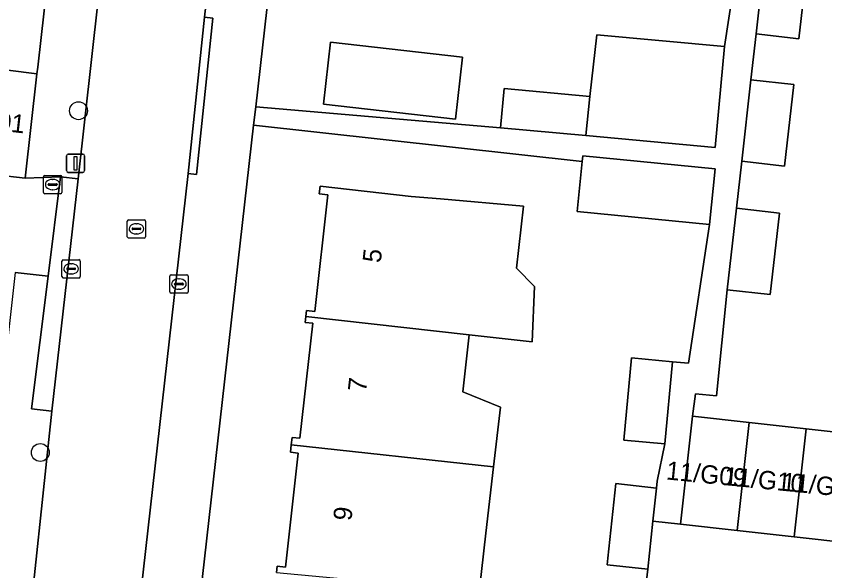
# Model space of a CAD drawing. Extents: x 162396 to 163643, y 386452 to 387406.
# Drawn here: x 162508.79 to 162552.91, y 386515.6 to 386545.84 of the extents above; entities that cross this region are included whole.
import ezdxf

# ---------------------------------------------------------------- set-up
doc = ezdxf.new("R2010")
doc.units = 0
for name, color, linetype in [('IMGEO_Boom', 7, 'Continuous'), ('IMGEO_Brandkraan', 7, 'Continuous'), ('IMGEO_Erf', 7, 'Continuous'), ('IMGEO_Kolk', 7, 'Continuous'), ('IMGEO_Lichtmast', 7, 'Continuous'), ('IMGEO_Pand', 7, 'Continuous'), ('IMGEO_Pand_nummerreeks', 7, 'Continuous'), ('IMGEO_Rijbaan_lokaal_open', 7, 'Continuous'), ('IMGEO_Rioolput', 7, 'Continuous'), ('IMGEO_Voetpad_open', 7, 'Continuous')]:
    doc.layers.add(name, color=color, linetype=linetype)

msp = doc.modelspace()

# ---------------------------------------------------------------- linework, layer by layer
at = {"layer": 'IMGEO_Boom'}
for centre in [(162512.194, 386540.685), (162510.11, 386522.051)]:
    msp.add_circle(centre, 0.489, dxfattribs=at)
at = {"layer": 'IMGEO_Brandkraan'}
for p, q in [((162510.286, 386536.234), (162510.286, 386537.086)), ((162510.361, 386537.16), (162511.213, 386537.16)), ((162510.774, 386536.94), (162510.799, 386536.94)), ((162511.287, 386537.086), (162511.287, 386536.234)), ((162510.545, 386536.654), (162510.545, 386536.666)), ((162510.983, 386536.617), (162510.585, 386536.617)), ((162510.588, 386536.703), (162510.986, 386536.703)), ((162511.029, 386536.666), (162511.029, 386536.654)), ((162511.213, 386536.16), (162510.361, 386536.16)), ((162510.797, 386536.38), (162510.772, 386536.38))]:
    msp.add_line(p, q, dxfattribs=at)
for points in [[(162510.286, 386536.234), (162510.286, 386537.086)], [(162510.361, 386537.16), (162511.213, 386537.16)], [(162511.287, 386537.086), (162511.287, 386536.234)], [(162511.213, 386536.16), (162510.361, 386536.16)]]:
    msp.add_lwpolyline(points, dxfattribs=at)
for centre, radius, start, end in [((162510.363, 386537.084), 0.0765, 91.552, 178.448), ((162510.363, 386537.084), 0.0765, 91.552, 178.448), ((162511.211, 386537.084), 0.0765, 1.552, 88.448), ((162511.211, 386537.084), 0.0765, 1.552, 88.448), ((162510.585, 386536.663), 0.0403, 85.8775, 175.7526), ((162510.582, 386536.653), 0.0366, 178.938, 274.7102), ((162510.986, 386536.66), 0.043, 264.8664, 352.4533), ((162510.99, 386536.665), 0.0386, 1.7309, 96.639), ((162510.363, 386536.236), 0.0765, 181.552, 268.448), ((162510.363, 386536.236), 0.0765, 181.552, 268.448), ((162511.211, 386536.236), 0.0765, 271.552, 358.448), ((162511.211, 386536.236), 0.0765, 271.552, 358.448)]:
    msp.add_arc(centre, radius, start, end, dxfattribs=at)
for centre, major_axis, ratio, start_param, end_param in [((162510.773, 386536.66), (-0.387, 0.002), 0.722429, 4.712389, 7.853982), ((162510.798, 386536.66), (-0.39, 0.002), 0.717154, 1.570796, 4.712389)]:
    msp.add_ellipse(centre, major_axis=major_axis, ratio=ratio, start_param=start_param, end_param=end_param, dxfattribs=at)
at = {"layer": 'IMGEO_Erf'}
for points in [[(162524.519, 386564.392), (162521.861, 386540.899), (162535.218, 386539.757), (162535.415, 386541.892), (162540.097, 386541.459), (162540.465, 386544.831), (162547.435, 386544.188), (162548.346, 386550.142), (162545.019, 386550.506), (162543.942, 386548.46), (162540.74, 386548.81), (162540.967, 386550.888), (162537.679, 386551.247), (162536.966, 386549.168), (162533.949, 386549.498), (162531.689, 386549.745), (162526.718, 386550.288), (162527.054, 386553.366), (162527.241, 386553.345), (162528.173, 386561.866)], [(162574.538, 386558.007), (162550.87, 386560.831), (162550.407, 386556.13), (162552.744, 386555.866), (162552.241, 386551.42), (162549.904, 386551.684), (162549.657, 386549.324), (162551.994, 386549.06), (162551.491, 386544.614), (162549.154, 386544.878), (162548.875, 386542.374), (162551.212, 386542.11), (162550.709, 386537.664), (162548.372, 386537.928), (162548.091, 386535.369), (162550.428, 386535.105), (162549.925, 386530.659), (162547.588, 386530.923), (162546.99, 386525.139), (162545.856, 386525.247), (162545.693, 386524.04), (162548.789, 386523.693), (162551.885, 386523.346), (162554.981, 386523)], [(162543.719, 386520.109), (162543.759, 386520.491), (162544.182, 386522.518), (162541.942, 386522.728), (162542.362, 386527.211), (162544.602, 386527.001), (162545.478, 386526.922), (162546.621, 386534.475), (162539.406, 386535.189), (162539.677, 386537.919), (162521.748, 386539.902), (162518.345, 386509.83)], [(162522.994, 386515.502), (162523.033, 386515.849), (162523.485, 386515.798), (162524.185, 386522.019), (162523.756, 386522.067), (162523.801, 386522.47), (162523.846, 386522.873), (162524.273, 386522.825), (162524.979, 386529.099), (162524.566, 386529.145), (162524.603, 386529.47), (162524.64, 386529.796), (162525.086, 386529.746), (162525.801, 386536.096), (162525.326, 386536.149), (162525.374, 386536.576), (162530.342, 386536.017), (162531.938, 386535.877), (162536.474, 386535.478), (162536.095, 386532.108), (162537.064, 386531.094), (162536.949, 386528.092), (162533.506, 386528.467), (162533.157, 386525.366), (162535.207, 386524.522), (162534.841, 386521.275), (162534.412, 386517.649), (162534.05, 386514.438)], [(162520.908, 386506.632), (162530.407, 386505.623), (162540.818, 386504.517), (162541.496, 386510.531), (162542.63, 386510.403), (162543.256, 386515.7), (162541.034, 386515.933), (162541.071, 386516.285), (162541.499, 386520.358), (162543.719, 386520.109)]]:
    msp.add_lwpolyline(points, dxfattribs=at)
msp.add_lwpolyline([(162533.138, 386543.61), (162532.756, 386540.229), (162525.559, 386541.043), (162525.941, 386544.424)], close=True, dxfattribs=at)
at = {"layer": 'IMGEO_Kolk'}
for p, q in [((162511.365, 386532.565), (162512.217, 386532.565)), ((162511.29, 386531.639), (162511.29, 386532.491)), ((162511.549, 386532.059), (162511.549, 386532.071)), ((162511.592, 386532.108), (162511.99, 386532.108)), ((162511.778, 386532.345), (162511.803, 386532.345)), ((162512.033, 386532.071), (162512.033, 386532.059)), ((162512.291, 386532.491), (162512.291, 386531.639)), ((162511.987, 386532.022), (162511.589, 386532.022)), ((162511.801, 386531.785), (162511.776, 386531.785)), ((162517.172, 386530.808), (162517.172, 386531.66)), ((162517.247, 386531.734), (162518.099, 386531.734)), ((162518.173, 386531.66), (162518.173, 386530.808)), ((162512.217, 386531.565), (162511.365, 386531.565)), ((162517.431, 386531.228), (162517.431, 386531.24)), ((162517.869, 386531.191), (162517.471, 386531.191)), ((162517.474, 386531.277), (162517.872, 386531.277)), ((162517.66, 386531.514), (162517.685, 386531.514)), ((162517.915, 386531.24), (162517.915, 386531.228)), ((162518.099, 386530.734), (162517.247, 386530.734)), ((162517.683, 386530.954), (162517.658, 386530.954))]:
    msp.add_line(p, q, dxfattribs=at)
for points in [[(162511.365, 386532.565), (162512.217, 386532.565)], [(162511.29, 386531.639), (162511.29, 386532.491)], [(162512.291, 386532.491), (162512.291, 386531.639)], [(162517.172, 386530.808), (162517.172, 386531.66)], [(162517.247, 386531.734), (162518.099, 386531.734)], [(162518.173, 386531.66), (162518.173, 386530.808)], [(162512.217, 386531.565), (162511.365, 386531.565)], [(162518.099, 386530.734), (162517.247, 386530.734)]]:
    msp.add_lwpolyline(points, dxfattribs=at)
for centre, radius, start, end in [((162511.367, 386532.489), 0.0765, 91.552, 178.448), ((162511.367, 386532.489), 0.0765, 91.552, 178.448), ((162512.215, 386532.489), 0.0765, 1.552, 88.448), ((162512.215, 386532.489), 0.0765, 1.552, 88.448), ((162511.589, 386532.068), 0.0403, 85.8775, 175.7526), ((162511.586, 386532.058), 0.0366, 178.938, 274.7102), ((162511.99, 386532.065), 0.043, 264.8664, 352.4533), ((162511.994, 386532.07), 0.0386, 1.7309, 96.639), ((162511.367, 386531.641), 0.0765, 181.552, 268.448), ((162511.367, 386531.641), 0.0765, 181.552, 268.448), ((162512.215, 386531.641), 0.0765, 271.552, 358.448), ((162512.215, 386531.641), 0.0765, 271.552, 358.448), ((162517.249, 386531.658), 0.0765, 91.552, 178.448), ((162517.249, 386531.658), 0.0765, 91.552, 178.448), ((162518.097, 386531.658), 0.0765, 1.552, 88.448), ((162518.097, 386531.658), 0.0765, 1.552, 88.448), ((162517.471, 386531.237), 0.0403, 85.8775, 175.7526), ((162517.468, 386531.227), 0.0366, 178.938, 274.7102), ((162517.872, 386531.234), 0.043, 264.8664, 352.4533), ((162517.876, 386531.239), 0.0386, 1.7309, 96.639), ((162517.249, 386530.81), 0.0765, 181.552, 268.448), ((162517.249, 386530.81), 0.0765, 181.552, 268.448), ((162518.097, 386530.81), 0.0765, 271.552, 358.448), ((162518.097, 386530.81), 0.0765, 271.552, 358.448)]:
    msp.add_arc(centre, radius, start, end, dxfattribs=at)
for centre, major_axis, ratio, start_param, end_param in [((162511.777, 386532.065), (-0.387, 0.002), 0.722429, 4.712389, 7.853982), ((162511.802, 386532.065), (-0.39, 0.002), 0.717154, 1.570796, 4.712389), ((162517.659, 386531.234), (-0.387, 0.002), 0.722429, 4.712389, 7.853982), ((162517.684, 386531.234), (-0.39, 0.002), 0.717154, 1.570796, 4.712389)]:
    msp.add_ellipse(centre, major_axis=major_axis, ratio=ratio, start_param=start_param, end_param=end_param, dxfattribs=at)
at = {"layer": 'IMGEO_Lichtmast'}
for p, q in [((162511.639, 386538.323), (162512.429, 386538.323)), ((162512.429, 386538.323), (162511.639, 386538.323)), ((162511.539, 386537.423), (162511.539, 386538.223)), ((162511.539, 386538.223), (162511.539, 386537.423)), ((162512.529, 386538.223), (162512.529, 386537.423)), ((162512.529, 386537.423), (162512.529, 386538.223)), ((162512.429, 386537.323), (162511.639, 386537.323)), ((162511.639, 386537.323), (162512.429, 386537.323))]:
    msp.add_line(p, q, dxfattribs=at)
msp.add_lwpolyline([(162511.959, 386538.198), (162512.109, 386538.198), (162512.109, 386537.448), (162511.959, 386537.448), (162511.959, 386538.198)], dxfattribs=at)
for centre, start, end in [((162511.639, 386538.223), 90, 180), ((162511.639, 386538.223), 90, 180), ((162512.429, 386538.223), 0, 90), ((162512.429, 386538.223), 360, 90), ((162511.639, 386537.423), 180, 270), ((162511.639, 386537.423), 180, 270), ((162512.429, 386537.423), 270, 0), ((162512.429, 386537.423), 270, 0)]:
    msp.add_arc(centre, 0.1, start, end, dxfattribs=at)
at = {"layer": 'IMGEO_Pand'}
for points in [[(162511.642, 386557.939), (162511.659, 386558.094), (162502.946, 386559.035), (162497.743, 386559.631), (162495.706, 386559.86), (162495.206, 386555.423), (162495.041, 386553.955), (162494.98, 386553.411), (162502.181, 386552.582), (162501.224, 386543.8), (162503.557, 386543.507), (162506.743, 386543.105), (162509.928, 386542.705), (162509.967, 386543.053)], [(162551.994, 386549.06), (162549.657, 386549.324), (162549.154, 386544.878), (162551.491, 386544.614)], [(162533.138, 386543.61), (162525.941, 386544.424), (162525.559, 386541.043), (162532.756, 386540.229)], [(162547.435, 386544.188), (162540.465, 386544.831), (162540.097, 386541.459), (162539.864, 386539.328), (162546.926, 386538.676)], [(162509.928, 386542.705), (162506.743, 386543.105), (162506.098, 386537.374), (162509.288, 386537.015)], [(162551.212, 386542.11), (162548.875, 386542.374), (162548.372, 386537.928), (162550.709, 386537.664)], [(162540.097, 386541.459), (162535.415, 386541.892), (162535.218, 386539.757), (162539.864, 386539.328)], [(162546.922, 386537.511), (162539.707, 386538.225), (162539.677, 386537.919), (162539.406, 386535.189), (162546.621, 386534.475)], [(162536.474, 386535.478), (162531.938, 386535.877), (162530.342, 386536.017), (162525.374, 386536.576), (162525.326, 386536.149), (162525.801, 386536.096), (162525.086, 386529.746), (162524.64, 386529.796), (162524.603, 386529.47), (162533.506, 386528.467), (162536.949, 386528.092), (162537.064, 386531.094), (162536.095, 386532.108)], [(162550.428, 386535.105), (162548.091, 386535.369), (162547.588, 386530.923), (162549.925, 386530.659)], [(162533.506, 386528.467), (162524.603, 386529.47), (162524.566, 386529.145), (162524.979, 386529.099), (162524.273, 386522.825), (162523.846, 386522.873), (162523.801, 386522.47), (162534.841, 386521.275), (162535.207, 386524.522), (162533.157, 386525.366)], [(162544.182, 386522.518), (162544.602, 386527.001), (162542.362, 386527.211), (162541.942, 386522.728)], [(162545.693, 386524.04), (162545.034, 386518.151), (162548.13, 386517.804), (162548.789, 386523.693)], [(162551.885, 386523.346), (162548.789, 386523.693), (162548.13, 386517.804), (162551.226, 386517.458)], [(162551.226, 386517.458), (162554.322, 386517.111), (162554.981, 386523), (162551.885, 386523.346)], [(162534.412, 386517.649), (162534.841, 386521.275), (162523.801, 386522.47), (162523.756, 386522.067), (162524.185, 386522.019), (162523.485, 386515.798), (162523.033, 386515.849), (162522.994, 386515.502), (162531.948, 386514.674), (162534.05, 386514.438)], [(162543.719, 386520.109), (162541.499, 386520.358), (162541.071, 386516.285), (162541.034, 386515.933), (162543.256, 386515.7), (162543.53, 386518.312)]]:
    msp.add_lwpolyline(points, close=True, dxfattribs=at)
at = {"layer": 'IMGEO_Rijbaan_lokaal_open'}
for points in [[(162538.542, 386630.425), (162538.637, 386630.689), (162539.168, 386632.177), (162533.31, 386634.243), (162520.916, 386598.567), (162519.409, 386592.958), (162517.768, 386586.008), (162516.873, 386578.96), (162512.175, 386536.978), (162510.746, 386524.31), (162509.296, 386510.744)], [(162515.091, 386509.886), (162518.171, 386537.265), (162519.073, 386545.782), (162523.205, 386581.894), (162523.891, 386586.28), (162524.764, 386590.188), (162526.069, 386595.297), (162527.576, 386600.04), (162538.542, 386630.425)]]:
    msp.add_lwpolyline(points, dxfattribs=at)
msp.add_lwpolyline([(162571.178, 386514.042), (162566.584, 386514.489), (162566.706, 386515.724), (162563.61, 386516.071), (162560.514, 386516.417), (162557.418, 386516.764), (162554.322, 386517.111), (162551.226, 386517.458), (162548.13, 386517.804), (162545.034, 386518.151), (162543.53, 386518.312), (162543.256, 386515.7), (162542.63, 386510.403), (162544.533, 386510.189), (162547.569, 386509.846), (162550.606, 386509.504), (162553.643, 386509.162), (162556.68, 386508.82), (162559.716, 386508.477), (162562.753, 386508.135), (162565.79, 386507.793), (162565.928, 386508.672), (162570.602, 386508.097)], close=True, dxfattribs=at)
at = {"layer": 'IMGEO_Rioolput'}
for p, q in [((162514.929, 386534.745), (162515.781, 386534.745)), ((162514.854, 386533.819), (162514.854, 386534.671)), ((162515.156, 386534.288), (162515.554, 386534.288)), ((162515.342, 386534.525), (162515.367, 386534.525)), ((162515.855, 386534.671), (162515.855, 386533.819)), ((162515.113, 386534.239), (162515.113, 386534.251)), ((162515.551, 386534.202), (162515.153, 386534.202)), ((162515.365, 386533.965), (162515.34, 386533.965)), ((162515.597, 386534.251), (162515.597, 386534.239)), ((162515.781, 386533.745), (162514.929, 386533.745))]:
    msp.add_line(p, q, dxfattribs=at)
for points in [[(162514.929, 386534.745), (162515.781, 386534.745)], [(162514.854, 386533.819), (162514.854, 386534.671)], [(162515.855, 386534.671), (162515.855, 386533.819)], [(162515.781, 386533.745), (162514.929, 386533.745)]]:
    msp.add_lwpolyline(points, dxfattribs=at)
for centre, radius, start, end in [((162514.931, 386534.669), 0.0765, 91.552, 178.448), ((162514.931, 386534.669), 0.0765, 91.552, 178.448), ((162515.779, 386534.669), 0.0765, 1.552, 88.448), ((162515.779, 386534.669), 0.0765, 1.552, 88.448), ((162515.153, 386534.248), 0.0403, 85.8775, 175.7526), ((162515.558, 386534.25), 0.0386, 1.7309, 96.639), ((162514.931, 386533.821), 0.0765, 181.552, 268.448), ((162514.931, 386533.821), 0.0765, 181.552, 268.448), ((162515.15, 386534.238), 0.0366, 178.938, 274.7102), ((162515.554, 386534.245), 0.043, 264.8664, 352.4533), ((162515.779, 386533.821), 0.0765, 271.552, 358.448), ((162515.779, 386533.821), 0.0765, 271.552, 358.448)]:
    msp.add_arc(centre, radius, start, end, dxfattribs=at)
for centre, major_axis, ratio, start_param, end_param in [((162515.341, 386534.245), (-0.387, 0.002), 0.722429, 4.712389, 7.853982), ((162515.366, 386534.245), (-0.39, 0.002), 0.717154, 1.570796, 4.712389)]:
    msp.add_ellipse(centre, major_axis=major_axis, ratio=ratio, start_param=start_param, end_param=end_param, dxfattribs=at)
at = {"layer": 'IMGEO_Voetpad_open'}
for points in [[(162516.873, 386578.96), (162517.768, 386586.008), (162519.409, 386592.958), (162520.916, 386598.567), (162533.31, 386634.243), (162530.479, 386635.242), (162529.602, 386632.75), (162529.537, 386632.564), (162525.216, 386619.885), (162520.116, 386604.921), (162518.289, 386599.414), (162517.104, 386595.322), (162516.634, 386593.698), (162515.418, 386587.914), (162515.018, 386587.956), (162513.322, 386572.875), (162511.659, 386558.094), (162511.642, 386557.939), (162509.967, 386543.053), (162509.928, 386542.705), (162509.288, 386537.015), (162511.213, 386537.082), (162512.175, 386536.978)], [(162519.531, 386545.731), (162519.073, 386545.782), (162518.171, 386537.265), (162518.635, 386537.214)], [(162512.175, 386536.978), (162511.213, 386537.082), (162510.539, 386531.667), (162509.639, 386524.426), (162510.746, 386524.31)]]:
    msp.add_lwpolyline(points, close=True, dxfattribs=at)
for points in [[(162526.67, 386582.569), (162527.699, 386588.467), (162529.53, 386595.31), (162530.664, 386598.974), (162541.261, 386629.271), (162541.368, 386629.555), (162541.641, 386630.284), (162539.168, 386632.177), (162538.637, 386630.689), (162538.542, 386630.425), (162527.576, 386600.04), (162528.05, 386599.883), (162526.543, 386595.14), (162526.069, 386595.297), (162524.764, 386590.188), (162525.256, 386590.1), (162523.697, 386581.806), (162523.205, 386581.894), (162519.073, 386545.782), (162519.531, 386545.731), (162518.635, 386537.214), (162518.171, 386537.265), (162515.091, 386509.886)], [(162518.345, 386509.83), (162521.748, 386539.902), (162521.861, 386540.899), (162524.519, 386564.392), (162524.497, 386564.462), (162525.515, 386573.155), (162525.584, 386573.206), (162526.67, 386582.569)], [(162548.346, 386550.142), (162547.435, 386544.188), (162546.926, 386538.676), (162539.864, 386539.328), (162535.218, 386539.757), (162521.861, 386540.899), (162521.748, 386539.902), (162539.677, 386537.919), (162539.707, 386538.225), (162546.922, 386537.511), (162546.621, 386534.475), (162545.478, 386526.922), (162544.602, 386527.001), (162544.182, 386522.518), (162543.759, 386520.491), (162543.719, 386520.109), (162543.53, 386518.312), (162545.034, 386518.151), (162545.693, 386524.04), (162545.856, 386525.247), (162546.99, 386525.139), (162547.588, 386530.923), (162548.091, 386535.369), (162548.372, 386537.928), (162548.875, 386542.374), (162549.154, 386544.878), (162549.657, 386549.324)], [(162508.736, 386531.868), (162510.539, 386531.667), (162511.213, 386537.082), (162509.288, 386537.015), (162506.098, 386537.374)], [(162509.296, 386510.744), (162510.746, 386524.31), (162509.639, 386524.426), (162510.539, 386531.667), (162508.736, 386531.868), (162505.167, 386500), (162505.108, 386499.473), (162500.348, 386500), (162500, 386500.039), (162499.111, 386500.137), (162496.117, 386500.466), (162495.544, 386495.264), (162500, 386494.773), (162510.731, 386493.592), (162525.614, 386491.953), (162540.596, 386490.304), (162555.461, 386488.667), (162570.324, 386487.031), (162575.176, 386486.432)]]:
    msp.add_lwpolyline(points, dxfattribs=at)

# ---------------------------------------------------------------- texts
at = {"layer": 'IMGEO_Pand_nummerreeks'}
for s, rotation, p in [('6/G01', 353.4339, (162505.598, 386539.864)), ('5', 83.5013, (162528.677, 386532.361)), ('7', 83.5013, (162527.876, 386525.328)), ('11/G09', 354.4278, (162544.22, 386520.587)), ('11/G10', 354.4278, (162547.368, 386520.28)), ('11/G11', 354.4278, (162550.525, 386519.972)), ('9', 83.5013, (162527.075, 386518.296))]:
    msp.add_text(s, height=1, rotation=rotation, dxfattribs=at).set_placement(p)

doc.saveas('drawing.dxf')
